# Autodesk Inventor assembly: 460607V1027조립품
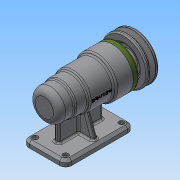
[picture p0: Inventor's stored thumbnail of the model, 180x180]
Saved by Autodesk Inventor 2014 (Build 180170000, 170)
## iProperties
Created: 2016-06
Part Number: 460607V1027조립품
Document SubType Name: Assembly
Designer: NET
Author: NET
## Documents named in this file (11)
- C:\Users\NET\Desktop\460607V1027\답안조립품.iam
- C:\Users\NET\Desktop\460607V1027\본체.ipt
- C:\Users\NET\Desktop\460607V1027\커버.ipt
- C:\Users\NET\Desktop\460607V1027\볼트 M4 x 12.ipt
- C:\Users\NET\Desktop\460607V1027\오일 실.ipt
- C:\Users\NET\Desktop\460607V1027\축.ipt
- C:\Users\NET\Desktop\460607V1027\키 5 x 5 x 16.ipt
- C:\Users\NET\Desktop\460607V1027\베어링 6004.ipt
- C:\Users\NET\Desktop\460607V1027\어댑터슬리브.ipt
- C:\Users\NET\Desktop\460607V1027\베어링 51202.ipt
- C:\Users\NET\Desktop\460607V1027\V벨트풀리.ipt
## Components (6 placed, 2 different names)
1. ISO 4762 M4 x 12:5
2. V벨트풀리:1 — 각도:1
3. ISO 4762 M4 x 12:1
4. ISO 4762 M4 x 12:2
5. ISO 4762 M4 x 12:3
6. ISO 4762 M4 x 12:4
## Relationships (1: Angle 1)
- 각도:1 [Angle]: V벨트풀리:1
